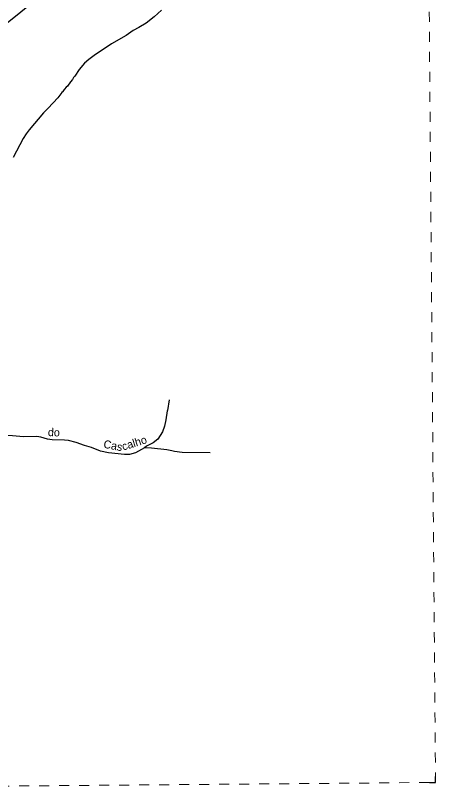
# Model space of a CAD drawing. Extents: x 344.9 to 371, y 7566.4 to 7594.3.
# Drawn here: x 366.76 to 370.96, y 7566.53 to 7574.28 of the extents above; entities that cross this region are included whole.
import ezdxf
from ezdxf.enums import TextEntityAlignment as Align

# ---------------------------------------------------------------- set-up
doc = ezdxf.new("R2010")
doc.units = 0
doc.header["$LTSCALE"] = 0.04
doc.linetypes.add('SHORT_DASHED', pattern=[2.7, 1.5, -1.2])
for name, color, linetype, lineweight in [('2', 7, 'Continuous', 25), ('53', 7, 'SHORT_DASHED', 13), ('55', 7, 'Continuous', 25), ('63', 7, 'Continuous', 25), ('7', 7, 'Continuous', 25)]:
    doc.layers.add(name, color=color, linetype=linetype, lineweight=lineweight)
doc.layers.add('61', color=7, linetype='Continuous')

msp = doc.modelspace()

# ---------------------------------------------------------------- linework, layer by layer
at = {"layer": '2'}
msp.add_lwpolyline([(368.2211, 7574.3293), (368.1474, 7574.264), (368.0662, 7574.2025), (367.992, 7574.1566), (367.9362, 7574.1268), (367.8661, 7574.079), (367.7194, 7573.9959), (367.5464, 7573.8782), (367.4947, 7573.8392), (367.4509, 7573.7997), (367.3977, 7573.7378), (367.3532, 7573.6711), (367.3389, 7573.6568), (367.331, 7573.6393), (367.3103, 7573.6163), (367.2794, 7573.571), (367.2667, 7573.5622), (367.2508, 7573.54), (367.2452, 7573.5392), (367.246, 7573.5313), (367.2365, 7573.5289), (367.2365, 7573.5178), (367.2246, 7573.5091), (367.1841, 7573.4558), (367.0872, 7573.3502), (367.0395, 7573.3037), (366.895, 7573.1346), (366.865, 7573.0951), (366.835, 7573.0478), (366.7354, 7572.8579)], dxfattribs=at)
at = {"layer": '53'}
for points in [[(370.9611, 7566.6143), (370.8886, 7575.5281), (370.883, 7576.2179), (370.8804, 7576.543)], [(361.4876, 7566.5338), (362.4145, 7566.542), (363.033, 7566.5474), (363.2025, 7566.5489), (363.4067, 7566.5507), (363.5305, 7566.5518), (364.0368, 7566.5561), (364.4239, 7566.5593), (364.4747, 7566.5598), (364.6393, 7566.5612), (366.1971, 7566.5742), (370.9611, 7566.6143)]]:
    msp.add_lwpolyline(points, dxfattribs=at)
at = {"layer": '55'}
msp.add_lwpolyline([(367.4854, 7574.8196), (367.1023, 7574.5489), (366.6611, 7574.1888), (366.3867, 7573.8395), (366.1501, 7573.478), (365.7032, 7572.9063), (365.6623, 7572.8301), (365.4153, 7572.3691)], dxfattribs=at)
at = {"layer": '63'}
msp.add_lwpolyline([(370.8995, 7566.6143), (370.9611, 7566.6143), (370.9611, 7566.675)], dxfattribs=at)
at = {"layer": '7'}
for points in [[(368.2958, 7570.4368), (368.2799, 7570.3303), (368.2767, 7570.3271), (368.264, 7570.239), (368.2513, 7570.1755), (368.2315, 7570.1183), (368.1846, 7570.0437), (368.1362, 7570.0079), (368.0695, 7569.9746), (368.0489, 7569.9586)], [(367.6891, 7569.9079), (367.6097, 7569.9245), (367.5208, 7569.9595), (367.4509, 7569.9801), (367.3683, 7570.0103), (367.2905, 7570.0294), (367.2508, 7570.0349), (367.1253, 7570.0365), (367.0809, 7570.0429), (367.0126, 7570.0627), (366.9729, 7570.0699), (366.8411, 7570.0675), (366.7299, 7570.0786), (366.6743, 7570.0802), (366.6409, 7570.077)], [(368.0489, 7569.9586), (367.9607, 7569.9087), (367.8988, 7569.8912), (367.8511, 7569.8896), (367.6891, 7569.9079)], [(368.7064, 7569.9071), (368.4276, 7569.9095), (368.3514, 7569.9198), (368.3228, 7569.9293), (368.272, 7569.9388), (368.1195, 7569.9555), (368.0489, 7569.9586)]]:
    msp.add_lwpolyline(points, dxfattribs=at)

# ---------------------------------------------------------------- texts
at = {"layer": '61'}
for s, rotation, p in [('do', 357.881, (367.1427, 7570.0729)), ('calho', 17.405, (367.9598, 7569.968)), ('Cas', 349.068, (367.7282, 7569.9414))]:
    msp.add_text(s, height=0.08, rotation=rotation, dxfattribs=at).set_placement(p, align=Align.CENTER)

doc.saveas('drawing.dxf')
